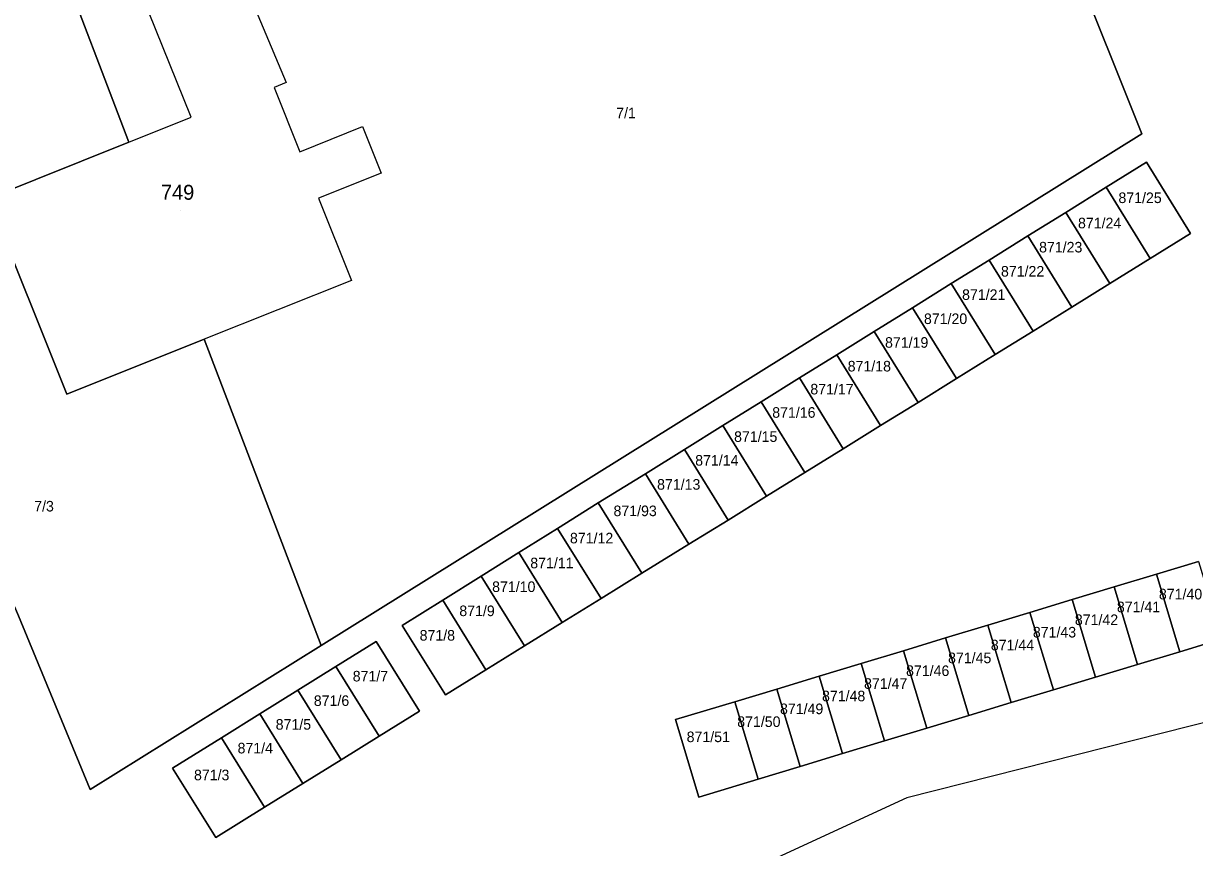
# Model space of a CAD drawing. Extents: x -873642 to -872917, y -1012962 to -1012567.
# Drawn here: x -873378.9 to -873284.9, y -1012894.5 to -1012828.2 of the extents above; entities that cross this region are included whole.
import ezdxf

# ---------------------------------------------------------------- set-up
doc = ezdxf.new("R2010")
doc.units = 0
for name, color, linetype in [('adresni_misto', 7, 'Continuous'), ('cisla_parcelni_kn', 7, 'Continuous'), ('cislo_domovni', 7, 'Continuous'), ('parcely_kn', 7, 'Continuous'), ('stavebni_objekty_ostatni', 7, 'Continuous'), ('stavebni_objekty_vyroba', 7, 'Continuous')]:
    doc.layers.add(name, color=color, linetype=linetype)

msp = doc.modelspace()

# ---------------------------------------------------------------- linework, layer by layer
at = {"layer": 'adresni_misto'}
msp.add_line((-873366.29, -1012843.31), (-873366.29, -1012843.31), dxfattribs=at)
at = {"layer": 'parcely_kn'}
for points in [[(-873379.34, -1012875.83), (-873373.58, -1012889.78), (-873355.03, -1012878.22), (-873289.09, -1012837.11), (-873306.1, -1012794.62), (-873364.45, -1012817.23), (-873371.7, -1012820.28), (-873376.39, -1012822.23), (-873378.27, -1012823.02), (-873378.61, -1012822.17), (-873388.38, -1012826.03), (-873398.8, -1012830.22), (-873398.3, -1012831.4), (-873382.99, -1012867.41)], [(-873379.34, -1012875.83), (-873373.58, -1012889.78), (-873355.03, -1012878.22), (-873289.09, -1012837.11), (-873306.1, -1012794.62), (-873364.45, -1012817.23), (-873371.7, -1012820.28), (-873376.39, -1012822.23), (-873378.27, -1012823.02), (-873378.61, -1012822.17), (-873388.38, -1012826.03), (-873398.8, -1012830.22), (-873398.3, -1012831.4), (-873382.99, -1012867.41)], [(-873364.45, -1012817.23), (-873306.1, -1012794.62), (-873289.09, -1012837.11), (-873355.03, -1012878.22), (-873364.42, -1012853.62), (-873375.46, -1012858.04), (-873381.76, -1012842.3), (-873370.46, -1012837.78), (-873376.39, -1012822.23), (-873371.7, -1012820.28)], [(-873364.45, -1012817.23), (-873306.1, -1012794.62), (-873289.09, -1012837.11), (-873355.03, -1012878.22), (-873364.42, -1012853.62), (-873375.46, -1012858.04), (-873381.76, -1012842.3), (-873370.46, -1012837.78), (-873376.39, -1012822.23), (-873371.7, -1012820.28)], [(-873355.03, -1012878.22), (-873373.58, -1012889.78), (-873379.34, -1012875.83), (-873382.99, -1012867.41), (-873398.3, -1012831.4), (-873398.8, -1012830.22), (-873388.38, -1012826.03), (-873378.61, -1012822.17), (-873378.27, -1012823.02), (-873376.39, -1012822.23), (-873370.46, -1012837.78), (-873381.76, -1012842.3), (-873375.46, -1012858.04), (-873364.42, -1012853.62)], [(-873355.03, -1012878.22), (-873373.58, -1012889.78), (-873379.34, -1012875.83), (-873382.99, -1012867.41), (-873398.3, -1012831.4), (-873398.8, -1012830.22), (-873388.38, -1012826.03), (-873378.61, -1012822.17), (-873378.27, -1012823.02), (-873376.39, -1012822.23), (-873370.46, -1012837.78), (-873381.76, -1012842.3), (-873375.46, -1012858.04), (-873364.42, -1012853.62)], [(-873325.47, -1012870.08), (-873322.33, -1012868.14), (-873319.24, -1012866.22), (-873316.16, -1012864.31), (-873313.09, -1012862.41), (-873310.08, -1012860.55), (-873307.07, -1012858.69), (-873303.99, -1012856.78), (-873300.87, -1012854.85), (-873297.82, -1012852.96), (-873294.71, -1012851.03), (-873291.65, -1012849.14), (-873288.42, -1012847.14), (-873285.18, -1012845.13), (-873288.73, -1012839.4), (-873291.97, -1012841.41), (-873295.19, -1012843.42), (-873298.25, -1012845.32), (-873301.35, -1012847.25), (-873304.4, -1012849.14), (-873307.51, -1012851.08), (-873310.6, -1012853), (-873313.59, -1012854.86), (-873316.6, -1012856.73), (-873319.67, -1012858.64), (-873322.74, -1012860.55), (-873325.84, -1012862.47), (-873328.97, -1012864.42), (-873332.76, -1012866.77), (-873336.03, -1012868.82), (-873339.14, -1012870.76), (-873342.16, -1012872.66), (-873345.25, -1012874.59), (-873348.5, -1012876.62), (-873345.04, -1012882.2), (-873341.78, -1012880.18), (-873338.68, -1012878.26), (-873335.65, -1012876.38), (-873332.53, -1012874.45), (-873329.25, -1012872.42)], [(-873325.47, -1012870.08), (-873322.33, -1012868.14), (-873319.24, -1012866.22), (-873316.16, -1012864.31), (-873313.09, -1012862.41), (-873310.08, -1012860.55), (-873307.07, -1012858.69), (-873303.99, -1012856.78), (-873300.87, -1012854.85), (-873297.82, -1012852.96), (-873294.71, -1012851.03), (-873291.65, -1012849.14), (-873288.42, -1012847.14), (-873285.18, -1012845.13), (-873288.73, -1012839.4), (-873291.97, -1012841.41), (-873295.19, -1012843.42), (-873298.25, -1012845.32), (-873301.35, -1012847.25), (-873304.4, -1012849.14), (-873307.51, -1012851.08), (-873310.6, -1012853), (-873313.59, -1012854.86), (-873316.6, -1012856.73), (-873319.67, -1012858.64), (-873322.74, -1012860.55), (-873325.84, -1012862.47), (-873328.97, -1012864.42), (-873332.76, -1012866.77), (-873336.03, -1012868.82), (-873339.14, -1012870.76), (-873342.16, -1012872.66), (-873345.25, -1012874.59), (-873348.5, -1012876.62), (-873345.04, -1012882.2), (-873341.78, -1012880.18), (-873338.68, -1012878.26), (-873335.65, -1012876.38), (-873332.53, -1012874.45), (-873329.25, -1012872.42)], [(-873285.18, -1012845.13), (-873288.42, -1012847.14), (-873291.97, -1012841.41), (-873288.73, -1012839.4)], [(-873285.18, -1012845.13), (-873288.42, -1012847.14), (-873291.97, -1012841.41), (-873288.73, -1012839.4)], [(-873291.97, -1012841.41), (-873288.42, -1012847.14), (-873291.65, -1012849.14), (-873295.19, -1012843.42)], [(-873291.97, -1012841.41), (-873288.42, -1012847.14), (-873291.65, -1012849.14), (-873295.19, -1012843.42)], [(-873291.65, -1012849.14), (-873294.71, -1012851.03), (-873298.25, -1012845.32), (-873295.19, -1012843.42)], [(-873291.65, -1012849.14), (-873294.71, -1012851.03), (-873298.25, -1012845.32), (-873295.19, -1012843.42)], [(-873298.25, -1012845.32), (-873294.71, -1012851.03), (-873297.82, -1012852.96), (-873301.35, -1012847.25)], [(-873298.25, -1012845.32), (-873294.71, -1012851.03), (-873297.82, -1012852.96), (-873301.35, -1012847.25)], [(-873301.35, -1012847.25), (-873297.82, -1012852.96), (-873300.87, -1012854.85), (-873304.4, -1012849.14)], [(-873301.35, -1012847.25), (-873297.82, -1012852.96), (-873300.87, -1012854.85), (-873304.4, -1012849.14)], [(-873304.4, -1012849.14), (-873300.87, -1012854.85), (-873303.99, -1012856.78), (-873307.51, -1012851.08)], [(-873304.4, -1012849.14), (-873300.87, -1012854.85), (-873303.99, -1012856.78), (-873307.51, -1012851.08)], [(-873307.51, -1012851.08), (-873303.99, -1012856.78), (-873307.07, -1012858.69), (-873310.6, -1012853)], [(-873307.51, -1012851.08), (-873303.99, -1012856.78), (-873307.07, -1012858.69), (-873310.6, -1012853)], [(-873310.6, -1012853), (-873307.07, -1012858.69), (-873310.08, -1012860.55), (-873313.59, -1012854.86)], [(-873310.6, -1012853), (-873307.07, -1012858.69), (-873310.08, -1012860.55), (-873313.59, -1012854.86)], [(-873313.59, -1012854.86), (-873310.08, -1012860.55), (-873313.09, -1012862.41), (-873316.6, -1012856.73)], [(-873313.59, -1012854.86), (-873310.08, -1012860.55), (-873313.09, -1012862.41), (-873316.6, -1012856.73)], [(-873313.09, -1012862.41), (-873316.16, -1012864.31), (-873319.67, -1012858.64), (-873316.6, -1012856.73)], [(-873313.09, -1012862.41), (-873316.16, -1012864.31), (-873319.67, -1012858.64), (-873316.6, -1012856.73)], [(-873319.67, -1012858.64), (-873316.16, -1012864.31), (-873319.24, -1012866.22), (-873322.74, -1012860.55)], [(-873319.67, -1012858.64), (-873316.16, -1012864.31), (-873319.24, -1012866.22), (-873322.74, -1012860.55)], [(-873322.74, -1012860.55), (-873319.24, -1012866.22), (-873322.33, -1012868.14), (-873325.84, -1012862.47)], [(-873322.74, -1012860.55), (-873319.24, -1012866.22), (-873322.33, -1012868.14), (-873325.84, -1012862.47)], [(-873325.84, -1012862.47), (-873322.33, -1012868.14), (-873325.47, -1012870.08), (-873328.97, -1012864.42)], [(-873325.84, -1012862.47), (-873322.33, -1012868.14), (-873325.47, -1012870.08), (-873328.97, -1012864.42)], [(-873328.97, -1012864.42), (-873325.47, -1012870.08), (-873329.25, -1012872.42), (-873332.76, -1012866.77)], [(-873328.97, -1012864.42), (-873325.47, -1012870.08), (-873329.25, -1012872.42), (-873332.76, -1012866.77)], [(-873332.76, -1012866.77), (-873329.25, -1012872.42), (-873332.53, -1012874.45), (-873336.03, -1012868.82)], [(-873332.76, -1012866.77), (-873329.25, -1012872.42), (-873332.53, -1012874.45), (-873336.03, -1012868.82)], [(-873336.03, -1012868.82), (-873332.53, -1012874.45), (-873335.65, -1012876.38), (-873339.14, -1012870.76)], [(-873336.03, -1012868.82), (-873332.53, -1012874.45), (-873335.65, -1012876.38), (-873339.14, -1012870.76)], [(-873339.14, -1012870.76), (-873335.65, -1012876.38), (-873338.68, -1012878.26), (-873342.16, -1012872.66)], [(-873339.14, -1012870.76), (-873335.65, -1012876.38), (-873338.68, -1012878.26), (-873342.16, -1012872.66)], [(-873287.92, -1012872.5), (-873284.53, -1012871.47), (-873282.65, -1012877.69), (-873286.04, -1012878.72)], [(-873287.92, -1012872.5), (-873284.53, -1012871.47), (-873282.65, -1012877.69), (-873286.04, -1012878.72)], [(-873342.16, -1012872.66), (-873338.68, -1012878.26), (-873341.78, -1012880.18), (-873345.25, -1012874.59)], [(-873342.16, -1012872.66), (-873338.68, -1012878.26), (-873341.78, -1012880.18), (-873345.25, -1012874.59)], [(-873291.31, -1012873.52), (-873287.92, -1012872.5), (-873286.04, -1012878.72), (-873289.43, -1012879.74)], [(-873291.31, -1012873.52), (-873287.92, -1012872.5), (-873286.04, -1012878.72), (-873289.43, -1012879.74)], [(-873294.69, -1012874.54), (-873291.31, -1012873.52), (-873289.43, -1012879.74), (-873292.81, -1012880.76)], [(-873294.69, -1012874.54), (-873291.31, -1012873.52), (-873289.43, -1012879.74), (-873292.81, -1012880.76)], [(-873345.25, -1012874.59), (-873341.78, -1012880.18), (-873345.04, -1012882.2), (-873348.5, -1012876.62)], [(-873345.25, -1012874.59), (-873341.78, -1012880.18), (-873345.04, -1012882.2), (-873348.5, -1012876.62)], [(-873298.08, -1012875.57), (-873294.69, -1012874.54), (-873292.81, -1012880.76), (-873296.2, -1012881.79)], [(-873298.08, -1012875.57), (-873294.69, -1012874.54), (-873292.81, -1012880.76), (-873296.2, -1012881.79)], [(-873301.47, -1012876.59), (-873298.08, -1012875.57), (-873296.2, -1012881.79), (-873299.59, -1012882.81)], [(-873301.47, -1012876.59), (-873298.08, -1012875.57), (-873296.2, -1012881.79), (-873299.59, -1012882.81)], [(-873304.86, -1012877.62), (-873301.47, -1012876.59), (-873299.59, -1012882.81), (-873302.98, -1012883.84)], [(-873304.86, -1012877.62), (-873301.47, -1012876.59), (-873299.59, -1012882.81), (-873302.98, -1012883.84)], [(-873363.48, -1012893.65), (-873359.56, -1012891.22), (-873356.48, -1012889.3), (-873353.42, -1012887.4), (-873350.35, -1012885.5), (-873347.11, -1012883.49), (-873350.59, -1012877.89), (-873353.83, -1012879.91), (-873356.89, -1012881.81), (-873359.95, -1012883.72), (-873363.03, -1012885.63), (-873366.95, -1012888.07)], [(-873363.48, -1012893.65), (-873359.56, -1012891.22), (-873356.48, -1012889.3), (-873353.42, -1012887.4), (-873350.35, -1012885.5), (-873347.11, -1012883.49), (-873350.59, -1012877.89), (-873353.83, -1012879.91), (-873356.89, -1012881.81), (-873359.95, -1012883.72), (-873363.03, -1012885.63), (-873366.95, -1012888.07)], [(-873347.11, -1012883.49), (-873350.35, -1012885.5), (-873353.83, -1012879.91), (-873350.59, -1012877.89)], [(-873347.11, -1012883.49), (-873350.35, -1012885.5), (-873353.83, -1012879.91), (-873350.59, -1012877.89)], [(-873308.25, -1012878.64), (-873304.86, -1012877.62), (-873302.98, -1012883.84), (-873306.37, -1012884.86)], [(-873308.25, -1012878.64), (-873304.86, -1012877.62), (-873302.98, -1012883.84), (-873306.37, -1012884.86)], [(-873311.64, -1012879.67), (-873308.25, -1012878.64), (-873306.37, -1012884.86), (-873309.76, -1012885.89)], [(-873311.64, -1012879.67), (-873308.25, -1012878.64), (-873306.37, -1012884.86), (-873309.76, -1012885.89)], [(-873353.83, -1012879.91), (-873350.35, -1012885.5), (-873353.42, -1012887.4), (-873356.89, -1012881.81)], [(-873353.83, -1012879.91), (-873350.35, -1012885.5), (-873353.42, -1012887.4), (-873356.89, -1012881.81)], [(-873315.02, -1012880.69), (-873311.64, -1012879.67), (-873309.76, -1012885.89), (-873313.14, -1012886.91)], [(-873315.02, -1012880.69), (-873311.64, -1012879.67), (-873309.76, -1012885.89), (-873313.14, -1012886.91)], [(-873318.41, -1012881.72), (-873315.02, -1012880.69), (-873313.14, -1012886.91), (-873316.53, -1012887.94)], [(-873318.41, -1012881.72), (-873315.02, -1012880.69), (-873313.14, -1012886.91), (-873316.53, -1012887.94)], [(-873356.89, -1012881.81), (-873353.42, -1012887.4), (-873356.48, -1012889.3), (-873359.95, -1012883.72)], [(-873356.89, -1012881.81), (-873353.42, -1012887.4), (-873356.48, -1012889.3), (-873359.95, -1012883.72)], [(-873321.8, -1012882.74), (-873318.41, -1012881.72), (-873316.53, -1012887.94), (-873319.92, -1012888.96)], [(-873321.8, -1012882.74), (-873318.41, -1012881.72), (-873316.53, -1012887.94), (-873319.92, -1012888.96)], [(-873326.56, -1012884.18), (-873321.8, -1012882.74), (-873319.92, -1012888.96), (-873324.68, -1012890.4)], [(-873326.56, -1012884.18), (-873321.8, -1012882.74), (-873319.92, -1012888.96), (-873324.68, -1012890.4)], [(-873359.95, -1012883.72), (-873356.48, -1012889.3), (-873359.56, -1012891.22), (-873363.03, -1012885.63)], [(-873359.95, -1012883.72), (-873356.48, -1012889.3), (-873359.56, -1012891.22), (-873363.03, -1012885.63)], [(-873363.03, -1012885.63), (-873359.56, -1012891.22), (-873363.48, -1012893.65), (-873366.95, -1012888.07)], [(-873363.03, -1012885.63), (-873359.56, -1012891.22), (-873363.48, -1012893.65), (-873366.95, -1012888.07)]]:
    msp.add_lwpolyline(points, close=True, dxfattribs=at)
for points in [[(-873149.77, -1012848.73), (-873202.95, -1012863.9), (-873307.96, -1012890.45), (-873318.36, -1012895.27), (-873328.54, -1012899.56), (-873340.69, -1012904.93), (-873416.15, -1012938.7), (-873417.98, -1012939.52), (-873435.72, -1012947.37), (-873445.76, -1012897.62), (-873478.14, -1012904.47), (-873481.91, -1012884.93)], [(-873149.77, -1012848.73), (-873202.95, -1012863.9), (-873307.96, -1012890.45), (-873318.36, -1012895.27), (-873328.54, -1012899.56), (-873340.69, -1012904.93), (-873416.15, -1012938.7), (-873417.98, -1012939.52), (-873435.72, -1012947.37), (-873445.76, -1012897.62), (-873478.14, -1012904.47), (-873481.91, -1012884.93)], [(-873219.616, -1012961.688), (-873165.87, -1012937.08), (-873157.54, -1012937.35), (-873150.44, -1012877.16), (-873149.77, -1012848.73), (-873202.95, -1012863.9), (-873307.96, -1012890.45), (-873318.36, -1012895.27), (-873296.12, -1012961.688)], [(-873219.616, -1012961.688), (-873165.87, -1012937.08), (-873157.54, -1012937.35), (-873150.44, -1012877.16), (-873149.77, -1012848.73), (-873202.95, -1012863.9), (-873307.96, -1012890.45), (-873318.36, -1012895.27), (-873296.12, -1012961.688)], [(-873284.53, -1012871.47), (-873287.92, -1012872.5), (-873291.31, -1012873.52), (-873294.69, -1012874.54), (-873298.08, -1012875.57), (-873301.47, -1012876.59), (-873304.86, -1012877.62), (-873308.25, -1012878.64), (-873311.64, -1012879.67), (-873315.02, -1012880.69), (-873318.41, -1012881.72), (-873321.8, -1012882.74), (-873326.56, -1012884.18), (-873324.68, -1012890.4), (-873319.92, -1012888.96), (-873316.53, -1012887.94), (-873313.14, -1012886.91), (-873309.76, -1012885.89), (-873306.37, -1012884.86), (-873302.98, -1012883.84), (-873299.59, -1012882.81), (-873296.2, -1012881.79), (-873292.81, -1012880.76), (-873289.43, -1012879.74), (-873286.04, -1012878.72), (-873282.65, -1012877.69)], [(-873284.53, -1012871.47), (-873287.92, -1012872.5), (-873291.31, -1012873.52), (-873294.69, -1012874.54), (-873298.08, -1012875.57), (-873301.47, -1012876.59), (-873304.86, -1012877.62), (-873308.25, -1012878.64), (-873311.64, -1012879.67), (-873315.02, -1012880.69), (-873318.41, -1012881.72), (-873321.8, -1012882.74), (-873326.56, -1012884.18), (-873324.68, -1012890.4), (-873319.92, -1012888.96), (-873316.53, -1012887.94), (-873313.14, -1012886.91), (-873309.76, -1012885.89), (-873306.37, -1012884.86), (-873302.98, -1012883.84), (-873299.59, -1012882.81), (-873296.2, -1012881.79), (-873292.81, -1012880.76), (-873289.43, -1012879.74), (-873286.04, -1012878.72), (-873282.65, -1012877.69)]]:
    msp.add_lwpolyline(points, dxfattribs=at)
at = {"layer": 'stavebni_objekty_ostatni'}
for points in [[(-873288.42, -1012847.14), (-873291.97, -1012841.41), (-873288.73, -1012839.4), (-873285.18, -1012845.13)], [(-873291.65, -1012849.14), (-873295.19, -1012843.42), (-873291.97, -1012841.41), (-873288.42, -1012847.14)], [(-873294.71, -1012851.03), (-873298.25, -1012845.32), (-873295.19, -1012843.42), (-873291.65, -1012849.14)], [(-873297.82, -1012852.96), (-873301.35, -1012847.25), (-873298.25, -1012845.32), (-873294.71, -1012851.03)], [(-873300.87, -1012854.85), (-873304.4, -1012849.14), (-873301.35, -1012847.25), (-873297.82, -1012852.96)], [(-873303.99, -1012856.78), (-873307.51, -1012851.08), (-873304.4, -1012849.14), (-873300.87, -1012854.85)], [(-873307.07, -1012858.69), (-873310.6, -1012853), (-873307.51, -1012851.08), (-873303.99, -1012856.78)], [(-873310.6, -1012853), (-873307.07, -1012858.69), (-873310.08, -1012860.55), (-873313.59, -1012854.86)], [(-873313.59, -1012854.86), (-873310.08, -1012860.55), (-873313.09, -1012862.41), (-873316.6, -1012856.73)], [(-873313.09, -1012862.41), (-873316.16, -1012864.31), (-873319.67, -1012858.64), (-873316.6, -1012856.73)], [(-873319.67, -1012858.64), (-873316.16, -1012864.31), (-873319.24, -1012866.22), (-873322.74, -1012860.55)], [(-873322.74, -1012860.55), (-873319.24, -1012866.22), (-873322.33, -1012868.14), (-873325.84, -1012862.47)], [(-873325.84, -1012862.47), (-873322.33, -1012868.14), (-873325.47, -1012870.08), (-873328.97, -1012864.42)], [(-873328.97, -1012864.42), (-873325.47, -1012870.08), (-873329.25, -1012872.42), (-873332.76, -1012866.77)], [(-873332.76, -1012866.77), (-873329.25, -1012872.42), (-873332.53, -1012874.45), (-873336.03, -1012868.82)], [(-873336.03, -1012868.82), (-873332.53, -1012874.45), (-873335.65, -1012876.38), (-873339.14, -1012870.76)], [(-873339.14, -1012870.76), (-873335.65, -1012876.38), (-873338.68, -1012878.26), (-873342.16, -1012872.66)], [(-873287.92, -1012872.5), (-873284.53, -1012871.47), (-873282.65, -1012877.69), (-873286.04, -1012878.72)], [(-873342.16, -1012872.66), (-873338.68, -1012878.26), (-873341.78, -1012880.18), (-873345.25, -1012874.59)], [(-873291.31, -1012873.52), (-873287.92, -1012872.5), (-873286.04, -1012878.72), (-873289.43, -1012879.74)], [(-873292.81, -1012880.76), (-873294.69, -1012874.54), (-873291.31, -1012873.52), (-873289.43, -1012879.74)], [(-873345.25, -1012874.59), (-873341.78, -1012880.18), (-873345.04, -1012882.2), (-873348.5, -1012876.62)], [(-873298.08, -1012875.57), (-873294.69, -1012874.54), (-873292.81, -1012880.76), (-873296.2, -1012881.79)], [(-873299.59, -1012882.81), (-873301.47, -1012876.59), (-873298.08, -1012875.57), (-873296.2, -1012881.79)], [(-873302.98, -1012883.84), (-873304.86, -1012877.62), (-873301.47, -1012876.59), (-873299.59, -1012882.81)], [(-873347.11, -1012883.49), (-873350.35, -1012885.5), (-873353.83, -1012879.91), (-873350.59, -1012877.89)], [(-873306.37, -1012884.86), (-873308.25, -1012878.64), (-873304.86, -1012877.62), (-873302.98, -1012883.84)], [(-873311.64, -1012879.67), (-873308.25, -1012878.64), (-873306.37, -1012884.86), (-873309.76, -1012885.89)], [(-873356.89, -1012881.81), (-873353.83, -1012879.91), (-873350.35, -1012885.5), (-873353.42, -1012887.4)], [(-873313.14, -1012886.91), (-873315.02, -1012880.69), (-873311.64, -1012879.67), (-873309.76, -1012885.89)], [(-873318.41, -1012881.72), (-873315.02, -1012880.69), (-873313.14, -1012886.91), (-873316.53, -1012887.94)], [(-873356.89, -1012881.81), (-873353.42, -1012887.4), (-873356.48, -1012889.3), (-873359.95, -1012883.72)], [(-873318.41, -1012881.72), (-873316.53, -1012887.94), (-873319.92, -1012888.96), (-873321.8, -1012882.74)], [(-873326.56, -1012884.18), (-873321.8, -1012882.74), (-873319.92, -1012888.96), (-873324.68, -1012890.4)], [(-873359.95, -1012883.72), (-873356.48, -1012889.3), (-873359.56, -1012891.22), (-873363.03, -1012885.63)], [(-873363.03, -1012885.63), (-873359.56, -1012891.22), (-873363.48, -1012893.65), (-873366.95, -1012888.07)]]:
    msp.add_lwpolyline(points, close=True, dxfattribs=at)
at = {"layer": 'stavebni_objekty_vyroba'}
msp.add_lwpolyline([(-873375.46, -1012858.04), (-873381.76, -1012842.3), (-873370.46, -1012837.78), (-873365.46, -1012835.78), (-873371.7, -1012820.28), (-873364.45, -1012817.23), (-873357.84, -1012832.99), (-873358.79, -1012833.39), (-873356.72, -1012838.55), (-873351.7, -1012836.52), (-873350.19, -1012840.26), (-873355.22, -1012842.29), (-873352.58, -1012848.89), (-873364.42, -1012853.62)], close=True, dxfattribs=at)

# ---------------------------------------------------------------- texts
at = {"layer": 'cisla_parcelni_kn'}
for s, p in [('7/1', (-873331.321, -1012835.863)), ('7/1', (-873331.321, -1012835.863)), ('871/25', (-873290.971, -1012842.675)), ('871/25', (-873290.971, -1012842.675)), ('871/24', (-873294.221, -1012844.706)), ('871/24', (-873294.221, -1012844.706)), ('871/23', (-873297.346, -1012846.644)), ('871/23', (-873297.346, -1012846.644)), ('871/22', (-873300.408, -1012848.581)), ('871/22', (-873300.408, -1012848.581)), ('871/21', (-873303.533, -1012850.456)), ('871/21', (-873303.533, -1012850.456)), ('871/20', (-873306.596, -1012852.394)), ('871/20', (-873306.596, -1012852.394)), ('871/19', (-873309.721, -1012854.3)), ('871/19', (-873309.721, -1012854.3)), ('871/18', (-873312.721, -1012856.206)), ('871/18', (-873312.721, -1012856.206)), ('871/17', (-873315.721, -1012858.05)), ('871/17', (-873315.721, -1012858.05)), ('871/16', (-873318.783, -1012859.925)), ('871/16', (-873318.783, -1012859.925)), ('871/15', (-873321.846, -1012861.863)), ('871/15', (-873321.846, -1012861.863)), ('871/14', (-873324.971, -1012863.769)), ('871/14', (-873324.971, -1012863.769)), ('871/13', (-873328.033, -1012865.706)), ('871/13', (-873328.033, -1012865.706)), ('7/3', (-873378.071, -1012867.456)), ('7/3', (-873378.071, -1012867.456)), ('871/93', (-873331.533, -1012867.831)), ('871/93', (-873331.533, -1012867.831)), ('871/12', (-873335.033, -1012870.019)), ('871/12', (-873335.033, -1012870.019)), ('871/11', (-873338.221, -1012872.019)), ('871/11', (-873338.221, -1012872.019)), ('871/10', (-873341.283, -1012873.925)), ('871/10', (-873341.283, -1012873.925)), ('871/40', (-873287.721, -1012874.519)), ('871/40', (-873287.721, -1012874.519)), ('871/9', (-873343.921, -1012875.863)), ('871/9', (-873343.921, -1012875.863)), ('871/41', (-873291.096, -1012875.55)), ('871/41', (-873291.096, -1012875.55)), ('871/42', (-873294.471, -1012876.581)), ('871/42', (-873294.471, -1012876.581)), ('871/8', (-873347.108, -1012877.831)), ('871/8', (-873347.108, -1012877.831)), ('871/43', (-873297.846, -1012877.581)), ('871/43', (-873297.846, -1012877.581)), ('871/44', (-873301.221, -1012878.613)), ('871/44', (-873301.221, -1012878.613)), ('871/45', (-873304.658, -1012879.644)), ('871/45', (-873304.658, -1012879.644)), ('871/46', (-873308.033, -1012880.675)), ('871/46', (-873308.033, -1012880.675)), ('871/7', (-873352.483, -1012881.113)), ('871/7', (-873352.483, -1012881.113)), ('871/47', (-873311.408, -1012881.706)), ('871/47', (-873311.408, -1012881.706)), ('871/6', (-873355.608, -1012883.081)), ('871/6', (-873355.608, -1012883.081)), ('871/48', (-873314.783, -1012882.706)), ('871/48', (-873314.783, -1012882.706)), ('871/49', (-873318.158, -1012883.738)), ('871/49', (-873318.158, -1012883.738)), ('871/5', (-873358.671, -1012884.988)), ('871/5', (-873358.671, -1012884.988)), ('871/50', (-873321.596, -1012884.769)), ('871/50', (-873321.596, -1012884.769)), ('871/51', (-873325.658, -1012885.988)), ('871/51', (-873325.658, -1012885.988)), ('871/4', (-873361.733, -1012886.894)), ('871/4', (-873361.733, -1012886.894)), ('871/3', (-873365.233, -1012889.05)), ('871/3', (-873365.233, -1012889.05))]:
    msp.add_text(s, height=0.85, dxfattribs=at).set_placement(p)
at = {"layer": 'cislo_domovni'}
msp.add_text('749', height=1.2, dxfattribs=at).set_placement((-873367.89, -1012842.41))

doc.saveas('drawing.dxf')
